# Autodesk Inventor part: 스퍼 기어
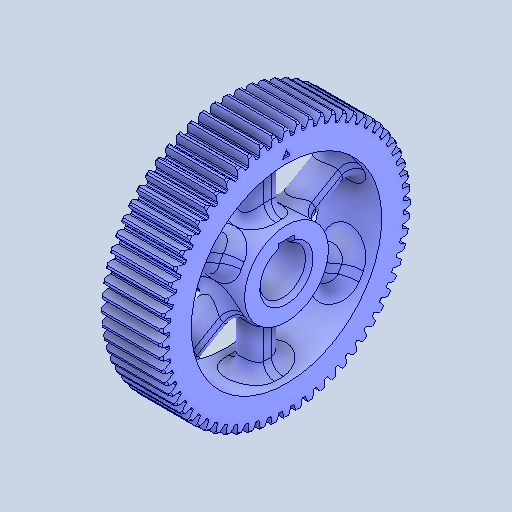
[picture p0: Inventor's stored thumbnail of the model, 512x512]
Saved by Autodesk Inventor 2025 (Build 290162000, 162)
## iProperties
Created: 2026-07
Part Number: 스퍼 기어
Material: 강철, 합금
Document SubType Name: Modeling
Designer: KDI
Density: 7.73 g/cm^3
Appearance: 기본값
Author: jhkim
Sending System: Autodesk Inventor 2027
Preprocessor: ST-DEVELOPER v20.1
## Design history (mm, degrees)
feature "솔리드1"
node "솔리드2"
